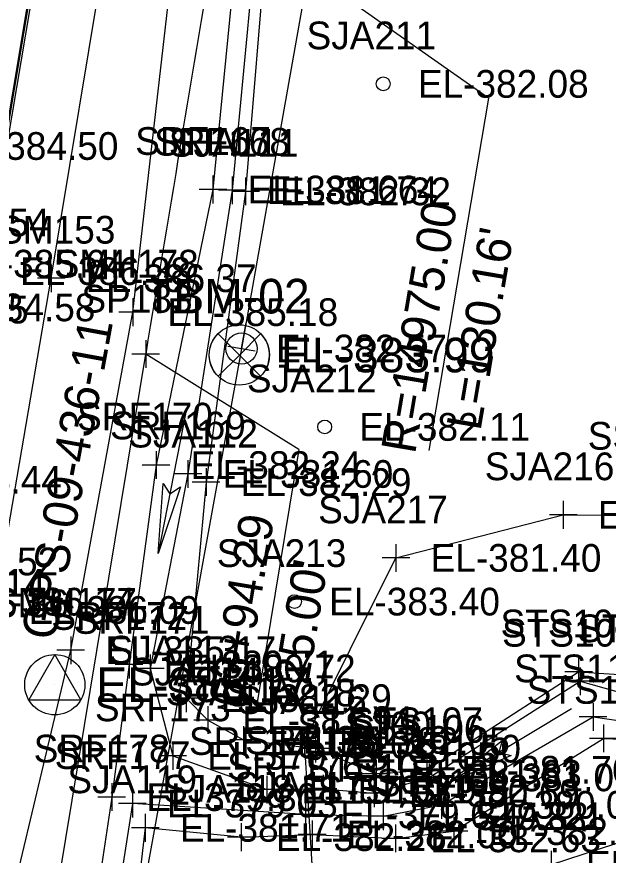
# Model space of a CAD drawing. Extents: x 1189978 to 1314812, y 571533 to 629339.
# Drawn here: x 1217655.7 to 1217741.2, y 622040.1 to 622161.2 of the extents above; entities that cross this region are included whole.
import ezdxf

# ---------------------------------------------------------------- set-up
doc = ezdxf.new("R2010")
doc.units = 0
for name, color, linetype in [('DESIGN - CENTERLINE - Proposed Text', 7, 'Continuous'), ('SURVEY - CENTERLINE - Preliminary', 7, 'Continuous'), ('SURVEY - CONTROL - Points - Elevations', 7, 'Continuous'), ('SURVEY - CONTROL with Text', 7, 'Continuous'), ('SURVEY - DRAINAGE - Area Shapes', 7, 'Continuous'), ('SURVEY - DRAINAGE - Bridge Hydraulic Data with Text', 7, 'Continuous'), ('SURVEY - DTM - Breaklines', 7, 'Continuous'), ('SURVEY - DTM - Breaklines - Points - Elevations', 7, 'Continuous'), ('SURVEY - DTM - Breaklines - Points - Locators', 7, 'Continuous'), ('SURVEY - DTM - Breaklines - Points - Numbers', 7, 'Continuous'), ('SURVEY - DTM - Spot Points - Elevations', 7, 'Continuous'), ('SURVEY - DTM - Spot Points - Locators', 7, 'Continuous'), ('SURVEY - DTM - Spot Points - Point Numbers', 7, 'Continuous'), ('SURVEY - PROPERTY - ROW Lines', 7, 'Continuous'), ('SURVEY - PROPERTY - ROW Lines - Points - Locators', 7, 'Continuous'), ('SURVEY - PROPERTY - ROW Lines - Points - Numbers', 7, 'Continuous'), ('SURVEY - PROPERTY - ROW Lines Text', 7, 'Continuous'), ('SURVEY - PROPERTY - Station and Offset Flags', 7, 'Continuous'), ('SURVEY - TRANSPORTATION - Roads', 7, 'Continuous'), ('SURVEY - TRANSPORTATION - Roads - Points - Elevations', 7, 'Continuous'), ('SURVEY - TRANSPORTATION - Roads - Points - Locators', 7, 'Continuous'), ('SURVEY - TRANSPORTATION - Roads - Points - Numbers', 7, 'Continuous'), ('SURVEY - UTILITIES - Electric (Overhead) with Text', 7, 'Continuous'), ('SURVEY - UTILITIES - Poles and Miscellaneous - Points - Elevations', 7, 'Continuous'), ('SURVEY - UTILITIES - Poles and Miscellaneous - Points - Locators', 7, 'Continuous'), ('SURVEY - UTILITIES - Poles and Miscellaneous with Text', 7, 'Continuous'), ('SURVEY - VEGETATION - Features - Points - Elevations', 7, 'Continuous'), ('SURVEY - VEGETATION - Features - Points - Locators', 7, 'Continuous'), ('SURVEY - VEGETATION - Features - Points - Numbers', 7, 'Continuous'), ('SURVEY - VEGETATION - Features with Text', 7, 'Continuous')]:
    doc.layers.add(name, color=color, linetype=linetype)

msp = doc.modelspace()

# ---------------------------------------------------------------- linework, layer by layer
at = {"layer": 'DESIGN - CENTERLINE - Proposed Text'}
msp.add_line((1217652.17, 622131.54), (1217660.31, 622180.87), dxfattribs=at)
at = {"layer": 'SURVEY - CENTERLINE - Preliminary'}
msp.add_arc((1232449.28, 619672.76), 15000, 170.125581, 170.6236, dxfattribs=at)
msp.add_arc((1232449.28, 619672.76), 15000, 170.125581, 170.6236, dxfattribs=at)
at = {"layer": 'SURVEY - CONTROL with Text'}
for p, q in [((1217684.81, 622115.43), (1217687.89, 622112.35)), ((1217687.89, 622112.35), (1217690.97, 622115.44)), ((1217684.82, 622109.29), (1217687.89, 622112.35)), ((1217687.89, 622112.35), (1217690.96, 622109.28)), ((1217661.22, 622069.1), (1217657.46, 622062.57)), ((1217664.99, 622062.57), (1217661.22, 622069.1)), ((1217661.22, 622064.75), (1217661.22, 622064.75)), ((1217657.46, 622062.57), (1217664.99, 622062.57))]:
    msp.add_line(p, q, dxfattribs=at)
for points in [[(1217684.82, 622115.41), (1217687.89, 622112.35), (1217684.83, 622109.29), (1217684.58, 622109.55), (1217684.32, 622109.88), (1217684.17, 622110.12), (1217683.99, 622110.44), (1217683.85, 622110.77), (1217683.75, 622111.05), (1217683.68, 622111.31), (1217683.61, 622111.6), (1217683.57, 622111.89), (1217683.55, 622112.15), (1217683.55, 622112.48), (1217683.56, 622112.75), (1217683.59, 622112.99), (1217683.62, 622113.19), (1217683.67, 622113.41), (1217683.75, 622113.69), (1217683.83, 622113.9), (1217683.92, 622114.13), (1217684.1, 622114.48), (1217684.29, 622114.81), (1217684.58, 622115.17)], [(1217690.96, 622115.42), (1217687.89, 622112.35), (1217690.95, 622109.28), (1217691.15, 622109.47), (1217691.37, 622109.75), (1217691.6, 622110.09), (1217691.74, 622110.34), (1217691.93, 622110.74), (1217692.03, 622111.03), (1217692.12, 622111.32), (1217692.17, 622111.55), (1217692.22, 622111.88), (1217692.24, 622112.12), (1217692.24, 622112.43), (1217692.23, 622112.74), (1217692.2, 622112.96), (1217692.15, 622113.23), (1217692.11, 622113.42), (1217692.04, 622113.68), (1217691.9, 622114.04), (1217691.81, 622114.25), (1217691.7, 622114.46), (1217691.49, 622114.81), (1217691.24, 622115.14)]]:
    msp.add_lwpolyline(points, close=True, dxfattribs=at)
for centre in [(1217687.89, 622112.36), (1217661.22, 622064.75)]:
    msp.add_circle(centre, 4.35, dxfattribs=at)
at = {"layer": 'SURVEY - DRAINAGE - Area Shapes'}
msp.add_line((1217415.87, 620731.68), (1218149.36, 625079.9), dxfattribs=at)
at = {"layer": 'SURVEY - DRAINAGE - Bridge Hydraulic Data with Text'}
for p, q in [((1217680.2, 622104.33), (1217676.17, 622083.71)), ((1217735.89, 622061.27), (1217717.88, 622050.45))]:
    msp.add_line(p, q, dxfattribs=at)
for points in [[(1217676.17, 622083.71), (1217676.87, 622093.81), (1217677.85, 622092.3), (1217679.38, 622093.32)], [(1217717.88, 622050.45), (1217725.85, 622056.7), (1217725.38, 622054.96), (1217727.16, 622054.51)]]:
    msp.add_lwpolyline(points, close=True, dxfattribs=at)
for points in [[(1217676.17, 622083.71), (1217676.87, 622093.81), (1217677.85, 622092.3), (1217679.38, 622093.32), (1217676.17, 622083.71)], [(1217717.88, 622050.45), (1217725.85, 622056.7), (1217725.38, 622054.96), (1217727.16, 622054.51), (1217717.88, 622050.45)]]:
    msp.add_lwpolyline(points, dxfattribs=at)
at = {"layer": 'SURVEY - DTM - Breaklines'}
for points in [[(1217591.74, 621765.73), (1217601.34, 621822.74), (1217608.84, 621869.52), (1217625.54, 621971.19), (1217634.6, 622026.63), (1217643.17, 622076.74), (1217651.21, 622124.47), (1217659.56, 622173.57), (1217668.17, 622224.78), (1217678.08, 622282.54), (1217688.16, 622340.37), (1217697.26, 622392.62), (1217705.46, 622440.01), (1217714.49, 622490.86), (1217723.28, 622541.33), (1217731.44, 622588.51), (1217739.96, 622637.78), (1217748.52, 622688.04), (1217748.57, 622688.21), (1217756.95, 622738.51)], [(1217604.56, 621765.51), (1217608.59, 621775.31), (1217618.98, 621822.73), (1217628.13, 621872.31), (1217636.41, 621920.88), (1217646.75, 621970.08), (1217652.31, 622022.79), (1217663.53, 622069.73), (1217672.49, 622118.54), (1217678.26, 622168.97), (1217683.24, 622219.55), (1217691.94, 622272.25), (1217701.2, 622320.93), (1217709.61, 622368.48), (1217718.57, 622415.45), (1217724.25, 622459.08), (1217730.45, 622491.37), (1217730.86, 622507.08)], [(1217734.86, 622491.68), (1217727.91, 622445.78), (1217720.64, 622398.43), (1217714.5, 622352.23), (1217706.13, 622302.11), (1217699.65, 622260.42), (1217693, 622212.18), (1217687.82, 622174.51), (1217684.08, 622136.25), (1217675.85, 622096.46), (1217671.96, 622067.67), (1217669.46, 622048.53), (1217661.22, 621993.63), (1217653.56, 621948.52), (1217646.28, 621917), (1217643.83, 621906.18), (1217644.06, 621905.86), (1217641.41, 621873.35), (1217633.96, 621824.29), (1217625.6, 621785.71), (1217619.08, 621762.41), (1217607.58, 621724.78)], [(1217739.88, 622491.64), (1217732.77, 622445.6), (1217725.75, 622396.67), (1217718.01, 622351.18), (1217711.55, 622301.06), (1217705.23, 622260.06), (1217697.9, 622211.38), (1217691.93, 622173.62), (1217688.78, 622135.98), (1217683.07, 622094), (1217680.22, 622062.81), (1217683.31, 622059.64), (1217688.49, 622056.78), (1217698.9, 622055.52)], [(1217737.99, 622491.58), (1217731.67, 622445.99), (1217724.08, 622397.71), (1217716.9, 622351.79), (1217709.45, 622301.8), (1217702.84, 622260.49), (1217695.06, 622212.22), (1217690.49, 622174.72), (1217686.87, 622136.14), (1217680.45, 622095.18), (1217675.01, 622067.1), (1217678.26, 622054.48), (1217691.84, 622049.62), (1217699.98, 622049.72)], [(1217698.9, 622055.52), (1217707.68, 622051.88), (1217714.98, 622052.47), (1217736.91, 622066.59), (1217747.93, 622065.89), (1217754.77, 622062.79), (1217782, 622069.74), (1217810.4, 622077.34)], [(1217699.98, 622049.72), (1217707.39, 622049.09), (1217715.32, 622051.37), (1217737.11, 622065.25), (1217753.89, 622060.54), (1217781.44, 622068.56), (1217808.88, 622074.94)], [(1217697.47, 622046.01), (1217708.67, 622045.75), (1217717.12, 622047.41), (1217739, 622060.11), (1217752.83, 622058.09), (1217782.2, 622064.21), (1217807.7, 622071.64)], [(1217688.16, 622042.74), (1217698.41, 622043.14), (1217710.47, 622042.57), (1217718.89, 622043.61), (1217740.49, 622057), (1217752.49, 622056.57), (1217782.9, 622062.19), (1217807.59, 622066.7)], [(1217697.47, 622046.01), (1217672.43, 622047.59), (1217663.85, 621992.57), (1217657.77, 621948.36), (1217649.39, 621917), (1217667.32, 621906.97), (1217691.53, 621893.28), (1217727.19, 621910.94), (1217768.29, 621913.65), (1217812.92, 621906.99)], [(1217688.16, 622042.74), (1217674.29, 622044.09), (1217668.19, 621992.33), (1217663.38, 621946.61), (1217653.5, 621919.01), (1217672.39, 621908.83), (1217708.13, 621910.46), (1217733.66, 621916.96), (1217767.69, 621917.46), (1217813.77, 621911.49)]]:
    msp.add_lwpolyline(points, dxfattribs=at)
at = {"layer": 'SURVEY - DTM - Breaklines - Points - Locators'}
for p, q in [((1217684.08, 622138.25), (1217684.08, 622134.25)), ((1217686.87, 622138.14), (1217686.87, 622134.14)), ((1217688.78, 622137.98), (1217688.78, 622133.98)), ((1217686.08, 622136.25), (1217682.08, 622136.25)), ((1217688.87, 622136.14), (1217684.87, 622136.14)), ((1217690.78, 622135.98), (1217686.78, 622135.98)), ((1217672.49, 622120.54), (1217672.49, 622116.54)), ((1217674.49, 622118.54), (1217670.49, 622118.54)), ((1217675.85, 622098.46), (1217675.85, 622094.46)), ((1217680.45, 622097.18), (1217680.45, 622093.18)), ((1217677.85, 622096.46), (1217673.85, 622096.46)), ((1217683.07, 622096), (1217683.07, 622092)), ((1217682.45, 622095.18), (1217678.45, 622095.18)), ((1217685.07, 622094), (1217681.07, 622094)), ((1217663.53, 622071.73), (1217663.53, 622067.73)), ((1217665.53, 622069.73), (1217661.53, 622069.73)), ((1217671.96, 622069.67), (1217671.96, 622065.67)), ((1217675.01, 622069.1), (1217675.01, 622065.1)), ((1217736.91, 622068.59), (1217736.91, 622064.59)), ((1217673.96, 622067.67), (1217669.96, 622067.67)), ((1217677.01, 622067.1), (1217673.01, 622067.1)), ((1217737.11, 622067.25), (1217737.11, 622063.25)), ((1217738.91, 622066.59), (1217734.91, 622066.59)), ((1217680.22, 622064.81), (1217680.22, 622060.81)), ((1217739.11, 622065.25), (1217735.11, 622065.25)), ((1217682.22, 622062.81), (1217678.22, 622062.81)), ((1217739, 622062.11), (1217739, 622058.11)), ((1217683.31, 622061.64), (1217683.31, 622057.64)), ((1217685.31, 622059.64), (1217681.31, 622059.64)), ((1217741, 622060.11), (1217737, 622060.11)), ((1217688.49, 622058.78), (1217688.49, 622054.78)), ((1217740.49, 622059), (1217740.49, 622055)), ((1217698.9, 622057.52), (1217698.9, 622053.52)), ((1217678.26, 622056.48), (1217678.26, 622052.48)), ((1217690.49, 622056.78), (1217686.49, 622056.78)), ((1217742.49, 622057), (1217738.49, 622057)), ((1217700.9, 622055.52), (1217696.9, 622055.52)), ((1217680.26, 622054.48), (1217676.26, 622054.48)), ((1217707.68, 622053.88), (1217707.68, 622049.88)), ((1217714.98, 622054.47), (1217714.98, 622050.47)), ((1217716.98, 622052.47), (1217712.98, 622052.47)), ((1217715.32, 622053.37), (1217715.32, 622049.37)), ((1217691.84, 622051.62), (1217691.84, 622047.62)), ((1217699.98, 622051.72), (1217699.98, 622047.72)), ((1217709.68, 622051.88), (1217705.68, 622051.88)), ((1217707.39, 622051.09), (1217707.39, 622047.09)), ((1217717.32, 622051.37), (1217713.32, 622051.37)), ((1217669.46, 622050.53), (1217669.46, 622046.53)), ((1217672.43, 622049.59), (1217672.43, 622045.59)), ((1217693.84, 622049.62), (1217689.84, 622049.62)), ((1217701.98, 622049.72), (1217697.98, 622049.72)), ((1217709.39, 622049.09), (1217705.39, 622049.09)), ((1217717.12, 622049.41), (1217717.12, 622045.41)), ((1217671.46, 622048.53), (1217667.46, 622048.53)), ((1217674.43, 622047.59), (1217670.43, 622047.59)), ((1217697.47, 622048.01), (1217697.47, 622044.01)), ((1217708.67, 622047.75), (1217708.67, 622043.75)), ((1217719.12, 622047.41), (1217715.12, 622047.41)), ((1217674.29, 622046.09), (1217674.29, 622042.09)), ((1217699.47, 622046.01), (1217695.47, 622046.01)), ((1217698.41, 622045.14), (1217698.41, 622041.14)), ((1217710.67, 622045.75), (1217706.67, 622045.75)), ((1217718.89, 622045.61), (1217718.89, 622041.61)), ((1217676.29, 622044.09), (1217672.29, 622044.09)), ((1217688.16, 622044.74), (1217688.16, 622040.74)), ((1217710.47, 622044.57), (1217710.47, 622040.57)), ((1217690.16, 622042.74), (1217686.16, 622042.74)), ((1217700.41, 622043.14), (1217696.41, 622043.14)), ((1217712.47, 622042.57), (1217708.47, 622042.57)), ((1217720.89, 622043.61), (1217716.89, 622043.61))]:
    msp.add_line(p, q, dxfattribs=at)
at = {"layer": 'SURVEY - DTM - Spot Points - Locators'}
for centre in [(1217708.68, 622151.5), (1217700.22, 622101.97), (1217695.86, 622076.75)]:
    msp.add_circle(centre, 1, dxfattribs=at)
at = {"layer": 'SURVEY - PROPERTY - ROW Lines'}
msp.add_line((1217606.4, 621700.95), (1217674.36, 622112.48), dxfattribs=at)
msp.add_arc((1232449.28, 619672.76), 14975, 170.125581, 170.623593, dxfattribs=at)
at = {"layer": 'SURVEY - PROPERTY - ROW Lines - Points - Locators'}
for p, q in [((1217674.36, 622114.48), (1217674.36, 622110.48)), ((1217674.36, 622114.48), (1217674.36, 622110.48)), ((1217676.36, 622112.48), (1217672.36, 622112.48)), ((1217676.36, 622112.48), (1217672.36, 622112.48))]:
    msp.add_line(p, q, dxfattribs=at)
at = {"layer": 'SURVEY - PROPERTY - ROW Lines Text'}
msp.add_line((1217723.91, 622149.42), (1217715.29, 622098.59), dxfattribs=at)
msp.add_lwpolyline([(1217723.91, 622149.42), (1217685.1, 622176.67)], dxfattribs=at)
at = {"layer": 'SURVEY - PROPERTY - Station and Offset Flags'}
msp.add_line((1217696.48, 622098.71), (1217690.3, 622061.32), dxfattribs=at)
msp.add_lwpolyline([(1217696.48, 622098.71), (1217674.36, 622112.48)], dxfattribs=at)
at = {"layer": 'SURVEY - TRANSPORTATION - Roads'}
msp.add_lwpolyline([(1217602.44, 621764.03), (1217601.61, 621764.4), (1217609.73, 621817.52), (1217617.85, 621867.88), (1217626.38, 621920.56), (1217634.53, 621969.83), (1217643.58, 622024.64), (1217652.44, 622075.54), (1217660.7, 622123.44), (1217668.82, 622172.59), (1217677.49, 622224.09), (1217697.4, 622338.83), (1217706.31, 622389.43), (1217714.67, 622438.11), (1217723.73, 622488.94), (1217732.47, 622539.47), (1217740.61, 622586), (1217749.34, 622636.23), (1217757.51, 622686.56)], dxfattribs=at)
at = {"layer": 'SURVEY - TRANSPORTATION - Roads - Points - Locators'}
for p, q in [((1217660.7, 622125.44), (1217660.7, 622121.44)), ((1217662.7, 622123.44), (1217658.7, 622123.44))]:
    msp.add_line(p, q, dxfattribs=at)
at = {"layer": 'SURVEY - UTILITIES - Electric (Overhead) with Text'}
msp.add_lwpolyline([(1217806.14, 622777), (1217743.09, 622422.64), (1217688.2, 622113.29), (1217626.83, 621775.19), (1217569.14, 621442.23), (1217508.83, 621100.02), (1217448.24, 620751.9)], dxfattribs=at)
at = {"layer": 'SURVEY - UTILITIES - Poles and Miscellaneous - Points - Locators'}
for p, q in [((1217688.55, 622115.26), (1217687.84, 622111.33)), ((1217686.23, 622113.65), (1217690.16, 622112.94))]:
    msp.add_line(p, q, dxfattribs=at)
at = {"layer": 'SURVEY - UTILITIES - Poles and Miscellaneous with Text'}
for q in [(1217688.87, 622116.98), (1217687.52, 622109.6)]:
    msp.add_line((1217688.2, 622113.29), q, dxfattribs=at)
msp.add_circle((1217688.2, 622113.29), 2.25, dxfattribs=at)
at = {"layer": 'SURVEY - VEGETATION - Features - Points - Locators'}
for p, q in [((1217734.69, 622091.28), (1217734.69, 622087.28)), ((1217736.69, 622089.28), (1217732.69, 622089.28)), ((1217710.52, 622085.06), (1217710.52, 622081.06)), ((1217712.52, 622083.06), (1217708.52, 622083.06)), ((1217697.28, 622058.62), (1217697.28, 622054.62)), ((1217699.28, 622056.62), (1217695.28, 622056.62)), ((1217732.95, 622040.76), (1217732.95, 622036.76))]:
    msp.add_line(p, q, dxfattribs=at)
at = {"layer": 'SURVEY - VEGETATION - Features with Text'}
msp.add_lwpolyline([(1217809.21, 622052.52), (1217788.75, 622054.38), (1217753.62, 622045.49), (1217732.95, 622038.76), (1217711.59, 622023.66), (1217699.22, 622025.69), (1217697.28, 622056.62), (1217710.52, 622083.06), (1217734.69, 622089.28), (1217769.88, 622089.01), (1217801.2, 622098.03)], dxfattribs=at)

# ---------------------------------------------------------------- texts
at = {"layer": 'SURVEY - CONTROL - Points - Elevations'}
for s, p in [('EL-383.99', (1217693.89, 622109.85)), ('EL-385.17', (1217667.22, 622062.25))]:
    msp.add_text(s, height=5, dxfattribs=at).set_placement(p)
at = {"layer": 'SURVEY - CONTROL with Text'}
msp.add_text('TBM-02', height=5, dxfattribs=at).set_placement((1217674.27, 622118.35))
msp.add_text('GPS-09-436-11', height=5, rotation=79.6922, dxfattribs=at).set_placement((1217661.26, 622070.99))
at = {"layer": 'SURVEY - DTM - Breaklines - Points - Elevations'}
for s, p in [('EL-384.50', (1217645.73, 622140.53)), ('EL-381.66', (1217689.08, 622134.25)), ('EL-381.74', (1217691.87, 622134.14)), ('EL-382.32', (1217693.78, 622133.98)), ('EL-386.38', (1217656.21, 622122.47)), ('EL-379.25', (1217632.75, 622116.91)), ('EL-385.18', (1217677.49, 622116.54)), ('EL-382.24', (1217680.85, 622094.46)), ('EL-381.60', (1217685.45, 622093.18)), ('EL-384.44', (1217637.56, 622092.35)), ('EL-382.29', (1217688.07, 622092)), ('EL-386.14', (1217648.17, 622074.74)), ('EL-385.17', (1217668.53, 622067.73)), ('EL-380.71', (1217676.96, 622065.67)), ('EL-380.72', (1217680.01, 622065.1)), ('EL-382.29', (1217685.22, 622060.81)), ('EL-381.94', (1217688.31, 622057.64)), ('EL-382.10', (1217693.49, 622054.78)), ('EL-381.50', (1217703.9, 622053.52)), ('EL-379.75', (1217683.26, 622052.48)), ('EL-381.63', (1217712.68, 622049.88)), ('EL-381.76', (1217719.98, 622050.47)), ('EL-381.01', (1217720.32, 622049.37)), ('EL-379.71', (1217696.84, 622047.62)), ('EL-379.92', (1217704.98, 622047.72)), ('EL-380.69', (1217712.39, 622047.09)), ('EL-379.30', (1217674.46, 622046.53)), ('EL-379.03', (1217677.43, 622045.59)), ('EL-380.07', (1217722.12, 622045.41)), ('EL-379.62', (1217702.47, 622044.01)), ('EL-379.82', (1217713.67, 622043.75)), ('EL-381.71', (1217679.29, 622042.09)), ('EL-382.00', (1217703.41, 622041.14)), ('EL-382.80', (1217723.89, 622041.61)), ('EL-382.26', (1217693.16, 622040.74)), ('EL-382.63', (1217715.47, 622040.57))]:
    msp.add_text(s, height=4, dxfattribs=at).set_placement(p)
at = {"layer": 'SURVEY - DTM - Breaklines - Points - Numbers'}
for s, p in [('SRF167', (1217672.84, 622141.25)), ('SRF168', (1217675.58, 622141.14)), ('SJA111', (1217677.7, 622140.98)), ('SSM154', (1217639.97, 622129.47)), ('SMH178', (1217661.2, 622123.54)), ('SRF170', (1217664.44, 622101.46)), ('SRF169', (1217669.2, 622100.18)), ('SJA112', (1217671.83, 622099)), ('SMH177', (1217652.29, 622074.73)), ('SRF172', (1217660.72, 622072.67)), ('SRF171', (1217663.93, 622072.1)), ('STS108', (1217725.62, 622071.59)), ('STS109', (1217725.85, 622070.25)), ('STS112', (1217736.69, 622070.89)), ('SJA113', (1217668.98, 622067.81)), ('STS110', (1217727.59, 622065.11)), ('SJA114', (1217672.07, 622064.64)), ('SJA115', (1217677.25, 622061.78)), ('STS111', (1217729.4, 622062)), ('SJA116', (1217687.55, 622060.52)), ('SRF173', (1217667.02, 622059.48)), ('STS100', (1217696.27, 622056.88)), ('STS107', (1217703.74, 622057.47)), ('STS106', (1217703.97, 622056.37)), ('SRF174', (1217680.6, 622054.62)), ('SRF175', (1217688.74, 622054.72)), ('SRF178', (1217658.17, 622053.53)), ('STS101', (1217696.3, 622054.09)), ('SRF177', (1217661.19, 622052.59)), ('STS105', (1217705.88, 622052.41)), ('SRF176', (1217686.12, 622051.01)), ('STS102', (1217697.43, 622050.75)), ('SJA119', (1217663.04, 622049.09)), ('SJA117', (1217687.17, 622048.14)), ('STS104', (1217707.65, 622048.61)), ('SJA118', (1217676.87, 622047.74)), ('STS103', (1217699.23, 622047.57))]:
    msp.add_text(s, height=4, dxfattribs=at).set_placement(p)
at = {"layer": 'SURVEY - DTM - Spot Points - Elevations'}
for s, p in [('EL-382.08', (1217713.68, 622149.5)), ('EL-382.11', (1217705.22, 622099.97)), ('EL-383.40', (1217700.86, 622074.75))]:
    msp.add_text(s, height=4, dxfattribs=at).set_placement(p)
at = {"layer": 'SURVEY - DTM - Spot Points - Point Numbers'}
for s, p in [('SJA211', (1217697.6, 622156.5)), ('SJA212', (1217688.98, 622106.97)), ('SSM471', (1217738.23, 622098.69)), ('SJA213', (1217684.62, 622081.75))]:
    msp.add_text(s, height=4, dxfattribs=at).set_placement(p)
at = {"layer": 'SURVEY - PROPERTY - ROW Lines - Points - Numbers'}
msp.add_text('SP183', height=4, dxfattribs=at).set_placement((1217665.07, 622118.48))
at = {"layer": 'SURVEY - PROPERTY - ROW Lines Text'}
for s, p in [("R=14975.00'", (1217713.27, 622097.94)), ("L=130.16'", (1217722.72, 622101.28))]:
    msp.add_text(s, height=5, rotation=80.3746, dxfattribs=at).set_placement(p)
at = {"layer": 'SURVEY - PROPERTY - Station and Offset Flags'}
for s, p in [('63+94.29', (1217688.38, 622061.2)), ("25.00'", (1217697.8, 622064.53))]:
    msp.add_text(s, height=5, rotation=80.6236, dxfattribs=at).set_placement(p)
at = {"layer": 'SURVEY - TRANSPORTATION - Roads - Points - Elevations'}
for s, p in [('EL-385.64', (1217646.88, 622123.54)), ('EL-386.37', (1217665.7, 622121.44)), ('EL-385.36', (1217638.57, 622074.49)), ('EL-386.09', (1217657.44, 622073.54))]:
    msp.add_text(s, height=4, dxfattribs=at).set_placement(p)
at = {"layer": 'SURVEY - TRANSPORTATION - Roads - Points - Numbers'}
for s, p in [('SSM153', (1217649.46, 622128.44)), ('SSM152', (1217641.2, 622080.54))]:
    msp.add_text(s, height=4, dxfattribs=at).set_placement(p)
at = {"layer": 'SURVEY - UTILITIES - Poles and Miscellaneous - Points - Elevations'}
msp.add_text('EL-382.57', height=4, dxfattribs=at).set_placement((1217693.2, 622111.29))
at = {"layer": 'SURVEY - VEGETATION - Features - Points - Elevations'}
for s, p in [('EL-384.58', (1217642.41, 622117.23)), ('EL-382.26', (1217739.69, 622087.28)), ('EL-381.40', (1217715.52, 622081.06)), ('EL-384.14', (1217635.2, 622077.47)), ('EL-382.05', (1217702.28, 622054.62)), ('EL-382.55', (1217737.95, 622036.76))]:
    msp.add_text(s, height=4, dxfattribs=at).set_placement(p)
at = {"layer": 'SURVEY - VEGETATION - Features - Points - Numbers'}
for s, p in [('SJA216', (1217723.34, 622094.28)), ('SJA217', (1217699.28, 622088.06)), ('SJA218', (1217685.99, 622061.62)), ('SJA221', (1217721.87, 622043.76))]:
    msp.add_text(s, height=4, dxfattribs=at).set_placement(p)

doc.saveas('drawing.dxf')
